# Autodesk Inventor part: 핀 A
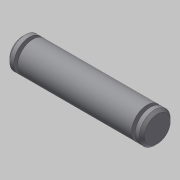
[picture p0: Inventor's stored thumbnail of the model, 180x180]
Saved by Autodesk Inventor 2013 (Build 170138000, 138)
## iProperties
Created: 2020-02
Part Number: 핀 A
Material: 스테인리스강
Document SubType Name: Modeling
Designer: mduedu
Density: 1 g/cm^3
Author: mduedu
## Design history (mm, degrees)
sketch "스케치1"
  geometry: L1 (0, 0)-(26, 0); L2 (26, 0)-(26, 3); L3 (26, 3)-(0, 3); L4 (0, 3)-(0, 0)
  constraints: 8 end point, 2 parallel, 1 horizontal, 1 perpendicular
  dimensions: "d0" = 26 distance of L2.end L3.end; "d2" = 6 diameter of L3 L1
revolve "회전1" sketch "스케치1" stored, may be unused: angle "d3" = 90 deg
sketch "스케치2"
  geometry: L1 (0, -3)-(0, 3) reference; L2 (0, 3)-(26, 3) reference; L3 (26, 3)-(26, -3) reference; L4 (26, -3)-(0, -3) reference; L5 (0, 0)-(26, 0); L6 (1.3, 3)-(2, 3); L7 (2, 3)-(2, 2); L8 (2, 2)-(1.3, 2); L9 (1.3, 2)-(1.3, 3)
  constraints: 10 end point, 2 parallel, 1 horizontal, 1 midpoint, 1 perpendicular, 1 point on line
  dimensions: "d4" = 4 diameter of L8 L5; "d6" = 1.3 distance between parallel lines of L9 L1; "d7" = 0.7 distance between parallel lines of L7 L9
revolve "회전2" sketch "스케치2" stored, may be unused: angle "d8" = 90 deg
node "작업 평면1"
chamfer "모따기1" distance "d9" = 0.5; stored, may be unused: second distance "d10" = 2, angle "d11" = 45 deg
node "솔리드1"
mirror "대칭1"
node "절단 모서리 투영1"
